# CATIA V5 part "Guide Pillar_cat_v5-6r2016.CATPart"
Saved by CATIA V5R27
Part number: Guide Pillar
Bounding box of the stored display mesh (mm): x 82.5 to 107.5, y 17.51 to 42.49, z 0 to 200
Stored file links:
  E:\_Deepak\2017_Deepak\CATIA\Resources\Tutorial Files\Tutorials\c12_catia_v5_6r2015_tut\c12tut2\Guide Pillar_cat_v5-6r2016.CATPart
  E:\_Deepak\2017_Deepak\CATIA\Resources\Tutorial Files\Tutorials\c12_catia_v5_6r2015_tut\c12tut2\Assembly_cat_v5-6r2016.CATProduct
  D:\CATIA V5R21 E-RESOURCES\CATIA-V5R21\catia-v5r21-Tut\c12-catia-v5r21-tut\c12-catia-v5r21-tut02\Bottom Plate.CATPart
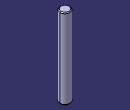
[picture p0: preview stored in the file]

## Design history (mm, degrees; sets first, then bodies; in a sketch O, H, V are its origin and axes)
Set1
  DatumSurface1: linked copy from another document
  DatumCurve1: linked copy from another document
Body1 (main body)
  Sketch1 on face of DatumSurface1, origin (0, 0, 0), H (1, 0, 0), V (0, 1, 0)
    projected circle E1 centre (95, 30) radius 12.5 from edge of DatumCurve1
  Pad1: profile Sketch1, direction (0, 0, 1), length 200
  Chamfer1: length 2, angle 45, on edge [face of Pad1 | face of Pad1] (x2)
